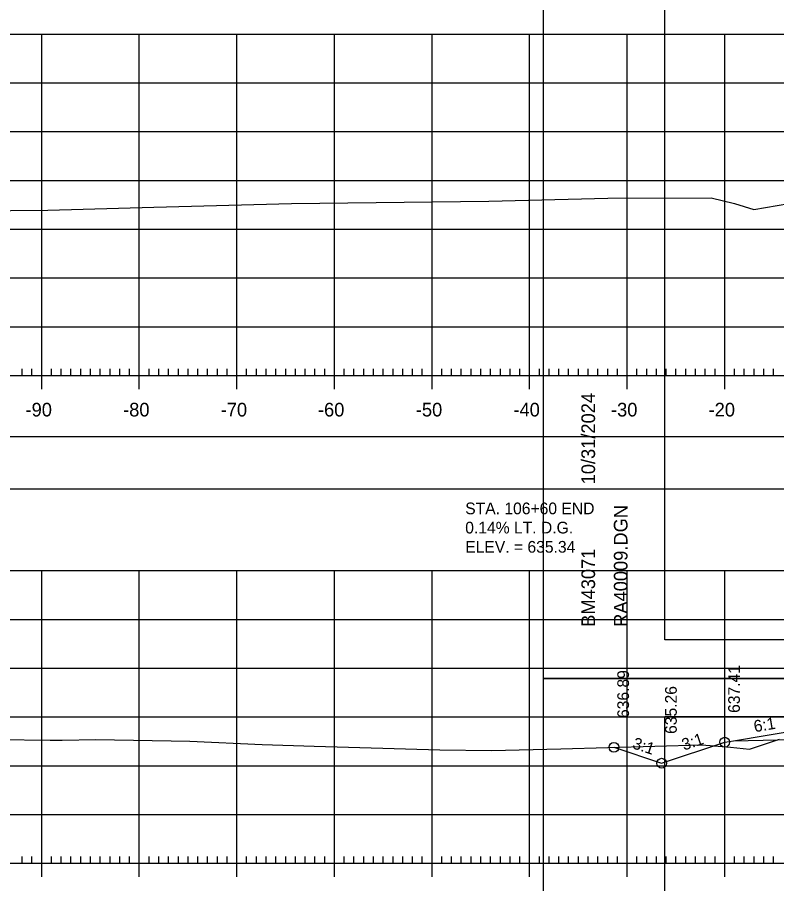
# Model space of a CAD drawing. Extents: x 1381471 to 1382703, y 370300 to 371487.
# Drawn here: x 1381912.3 to 1381990.1, y 371039.5 to 371128.3 of the extents above; entities that cross this region are included whole.
import ezdxf

# ---------------------------------------------------------------- set-up
doc = ezdxf.new("R2010")
doc.units = 0
for name, color, linetype in [('Level 18', 7, 'Continuous'), ('Level 2', 7, 'Continuous'), ('Level 20', 7, 'Continuous'), ('Level 22', 7, 'Continuous'), ('Level 26', 7, 'Continuous'), ('Level 4', 7, 'Continuous'), ('Level 41', 7, 'Continuous'), ('Level 42', 7, 'Continuous'), ('Level 45', 7, 'Continuous'), ('Level 5', 7, 'Continuous'), ('Level 6', 7, 'Continuous')]:
    doc.layers.add(name, color=color, linetype=linetype)

msp = doc.modelspace()

# ---------------------------------------------------------------- linework, layer by layer
at = {"layer": 'Level 18'}
for points in [[(1381864.772, 371108.078), (1381865.976, 371108.088), (1381873.71, 371108.053), (1381885.41, 371108.295), (1381892.552, 371108.284), (1381915.382, 371108.479), (1381926.247, 371108.792), (1381940.386, 371109.168), (1381960.604, 371109.403), (1381972.783, 371109.721), (1381983.377, 371109.751), (1381985.775, 371109.162), (1381987.759, 371108.574), (1381991.332, 371109.19)], [(1381864.772, 371053.733), (1381866.819, 371053.78), (1381877.788, 371053.995), (1381883.886, 371054.108), (1381892.68, 371054.277), (1381899.926, 371054.23), (1381905.023, 371054.302), (1381915.624, 371054.159), (1381916.856, 371054.17), (1381920.322, 371054.218), (1381929.942, 371054.047), (1381937.36, 371053.717), (1381942.702, 371053.56), (1381955.573, 371053.183), (1381960.873, 371053.094), (1381967.986, 371053.284), (1381982.422, 371053.683), (1381985.357, 371053.452), (1381987.306, 371053.246), (1381990.383, 371054.284)]]:
    msp.add_lwpolyline(points, dxfattribs=at)
at = {"layer": 'Level 2'}
msp.add_lwpolyline([(1381985.66, 371054.107), (1381994.762, 371054.289), (1381994.772, 371055.206), (1382004.772, 371055.406), (1382014.772, 371055.202), (1382014.782, 371054.286), (1382023.908, 371054.103)], dxfattribs=at)
at = {"layer": 'Level 20'}
msp.add_lwpolyline([(1381973.409, 371053.434), (1381978.303, 371051.803), (1381984.772, 371053.959), (1381985.66, 371054.107), (1381992.772, 371055.292), (1381994.772, 371055.372), (1382004.772, 371055.572), (1382014.772, 371055.372), (1382016.772, 371055.292), (1382023.908, 371054.103), (1382024.772, 371053.959), (1382031.554, 371051.698)], dxfattribs=at)
at = {"layer": 'Level 22'}
for p, q in [((1381864.772, 371126.544), (1382144.772, 371126.544)), ((1381914.772, 371091.544), (1381914.772, 371126.544)), ((1381924.772, 371091.544), (1381924.772, 371126.544)), ((1381934.772, 371091.544), (1381934.772, 371126.544)), ((1381944.772, 371091.544), (1381944.772, 371126.544)), ((1381954.772, 371091.544), (1381954.772, 371126.544)), ((1381964.772, 371091.544), (1381964.772, 371126.544)), ((1381974.772, 371091.544), (1381974.772, 371126.544)), ((1381984.772, 371091.544), (1381984.772, 371126.544)), ((1381864.772, 371121.544), (1382144.772, 371121.544)), ((1381864.772, 371116.544), (1382144.772, 371116.544)), ((1381864.772, 371111.544), (1382144.772, 371111.544)), ((1381864.772, 371106.544), (1382144.772, 371106.544)), ((1381864.772, 371101.544), (1382144.772, 371101.544)), ((1381864.772, 371096.544), (1382144.772, 371096.544)), ((1381864.772, 371091.544), (1382144.772, 371091.544)), ((1381864.772, 371071.544), (1382144.772, 371071.544)), ((1381914.772, 371041.544), (1381914.772, 371071.544)), ((1381924.772, 371041.544), (1381924.772, 371071.544)), ((1381934.772, 371041.544), (1381934.772, 371071.544)), ((1381944.772, 371041.544), (1381944.772, 371071.544)), ((1381954.772, 371041.544), (1381954.772, 371071.544)), ((1381964.772, 371041.544), (1381964.772, 371071.544)), ((1381974.772, 371041.544), (1381974.772, 371071.544)), ((1381984.772, 371041.544), (1381984.772, 371071.544)), ((1381864.772, 371066.544), (1382144.772, 371066.544)), ((1381864.772, 371061.544), (1382144.772, 371061.544)), ((1381864.772, 371056.544), (1382144.772, 371056.544)), ((1381864.772, 371051.544), (1382144.772, 371051.544)), ((1381864.772, 371046.544), (1382144.772, 371046.544)), ((1381864.772, 371041.544), (1382144.772, 371041.544))]:
    msp.add_line(p, q, dxfattribs=at)
at = {"layer": 'Level 26'}
for centre in [(1381984.772, 371053.959), (1381973.409, 371053.434), (1381978.303, 371051.803), (1381978.303, 371051.803)]:
    msp.add_circle(centre, 0.5, dxfattribs=at)
at = {"layer": 'Level 4'}
for p, q in [((1381914.772, 371090.144), (1381914.772, 371092.944)), ((1381924.772, 371090.144), (1381924.772, 371092.944)), ((1381934.772, 371090.144), (1381934.772, 371092.944)), ((1381944.772, 371090.144), (1381944.772, 371092.944)), ((1381954.772, 371090.144), (1381954.772, 371092.944)), ((1381964.772, 371090.144), (1381964.772, 371092.944)), ((1381974.772, 371090.144), (1381974.772, 371092.944)), ((1381984.772, 371090.144), (1381984.772, 371092.944)), ((1381864.772, 371091.544), (1382144.772, 371091.544)), ((1381912.772, 371091.544), (1381912.772, 371092.244)), ((1381913.772, 371091.544), (1381913.772, 371092.244)), ((1381915.772, 371091.544), (1381915.772, 371092.244)), ((1381916.772, 371091.544), (1381916.772, 371092.244)), ((1381917.772, 371091.544), (1381917.772, 371092.244)), ((1381918.772, 371091.544), (1381918.772, 371092.244)), ((1381919.772, 371091.544), (1381919.772, 371092.244)), ((1381920.772, 371091.544), (1381920.772, 371092.244)), ((1381921.772, 371091.544), (1381921.772, 371092.244)), ((1381922.772, 371091.544), (1381922.772, 371092.244)), ((1381923.772, 371091.544), (1381923.772, 371092.244)), ((1381925.772, 371091.544), (1381925.772, 371092.244)), ((1381926.772, 371091.544), (1381926.772, 371092.244)), ((1381927.772, 371091.544), (1381927.772, 371092.244)), ((1381928.772, 371091.544), (1381928.772, 371092.244)), ((1381929.772, 371091.544), (1381929.772, 371092.244)), ((1381930.772, 371091.544), (1381930.772, 371092.244)), ((1381931.772, 371091.544), (1381931.772, 371092.244)), ((1381932.772, 371091.544), (1381932.772, 371092.244)), ((1381933.772, 371091.544), (1381933.772, 371092.244)), ((1381935.772, 371091.544), (1381935.772, 371092.244)), ((1381936.772, 371091.544), (1381936.772, 371092.244)), ((1381937.772, 371091.544), (1381937.772, 371092.244)), ((1381938.772, 371091.544), (1381938.772, 371092.244)), ((1381939.772, 371091.544), (1381939.772, 371092.244)), ((1381940.772, 371091.544), (1381940.772, 371092.244)), ((1381941.772, 371091.544), (1381941.772, 371092.244)), ((1381942.772, 371091.544), (1381942.772, 371092.244)), ((1381943.772, 371091.544), (1381943.772, 371092.244)), ((1381945.772, 371091.544), (1381945.772, 371092.244)), ((1381946.772, 371091.544), (1381946.772, 371092.244)), ((1381947.772, 371091.544), (1381947.772, 371092.244)), ((1381948.772, 371091.544), (1381948.772, 371092.244)), ((1381949.772, 371091.544), (1381949.772, 371092.244)), ((1381950.772, 371091.544), (1381950.772, 371092.244)), ((1381951.772, 371091.544), (1381951.772, 371092.244)), ((1381952.772, 371091.544), (1381952.772, 371092.244)), ((1381953.772, 371091.544), (1381953.772, 371092.244)), ((1381955.772, 371091.544), (1381955.772, 371092.244)), ((1381956.772, 371091.544), (1381956.772, 371092.244)), ((1381957.772, 371091.544), (1381957.772, 371092.244)), ((1381958.772, 371091.544), (1381958.772, 371092.244)), ((1381959.772, 371091.544), (1381959.772, 371092.244)), ((1381960.772, 371091.544), (1381960.772, 371092.244)), ((1381961.772, 371091.544), (1381961.772, 371092.244)), ((1381962.772, 371091.544), (1381962.772, 371092.244)), ((1381963.772, 371091.544), (1381963.772, 371092.244)), ((1381965.772, 371091.544), (1381965.772, 371092.244)), ((1381966.772, 371091.544), (1381966.772, 371092.244)), ((1381967.772, 371091.544), (1381967.772, 371092.244)), ((1381968.772, 371091.544), (1381968.772, 371092.244)), ((1381969.772, 371091.544), (1381969.772, 371092.244)), ((1381970.772, 371091.544), (1381970.772, 371092.244)), ((1381971.772, 371091.544), (1381971.772, 371092.244)), ((1381972.772, 371091.544), (1381972.772, 371092.244)), ((1381973.772, 371091.544), (1381973.772, 371092.244)), ((1381975.772, 371091.544), (1381975.772, 371092.244)), ((1381976.772, 371091.544), (1381976.772, 371092.244)), ((1381977.772, 371091.544), (1381977.772, 371092.244)), ((1381978.772, 371091.544), (1381978.772, 371092.244)), ((1381979.772, 371091.544), (1381979.772, 371092.244)), ((1381980.772, 371091.544), (1381980.772, 371092.244)), ((1381981.772, 371091.544), (1381981.772, 371092.244)), ((1381982.772, 371091.544), (1381982.772, 371092.244)), ((1381983.772, 371091.544), (1381983.772, 371092.244)), ((1381985.772, 371091.544), (1381985.772, 371092.244)), ((1381986.772, 371091.544), (1381986.772, 371092.244)), ((1381987.772, 371091.544), (1381987.772, 371092.244)), ((1381988.772, 371091.544), (1381988.772, 371092.244)), ((1381989.772, 371091.544), (1381989.772, 371092.244)), ((1381914.772, 371040.144), (1381914.772, 371042.944)), ((1381924.772, 371040.144), (1381924.772, 371042.944)), ((1381934.772, 371040.144), (1381934.772, 371042.944)), ((1381944.772, 371040.144), (1381944.772, 371042.944)), ((1381954.772, 371040.144), (1381954.772, 371042.944)), ((1381964.772, 371040.144), (1381964.772, 371042.944)), ((1381974.772, 371040.144), (1381974.772, 371042.944)), ((1381984.772, 371040.144), (1381984.772, 371042.944)), ((1381912.772, 371041.544), (1381912.772, 371042.244)), ((1381913.772, 371041.544), (1381913.772, 371042.244)), ((1381915.772, 371041.544), (1381915.772, 371042.244)), ((1381916.772, 371041.544), (1381916.772, 371042.244)), ((1381917.772, 371041.544), (1381917.772, 371042.244)), ((1381918.772, 371041.544), (1381918.772, 371042.244)), ((1381919.772, 371041.544), (1381919.772, 371042.244)), ((1381920.772, 371041.544), (1381920.772, 371042.244)), ((1381921.772, 371041.544), (1381921.772, 371042.244)), ((1381922.772, 371041.544), (1381922.772, 371042.244)), ((1381923.772, 371041.544), (1381923.772, 371042.244)), ((1381925.772, 371041.544), (1381925.772, 371042.244)), ((1381926.772, 371041.544), (1381926.772, 371042.244)), ((1381927.772, 371041.544), (1381927.772, 371042.244)), ((1381928.772, 371041.544), (1381928.772, 371042.244)), ((1381929.772, 371041.544), (1381929.772, 371042.244)), ((1381930.772, 371041.544), (1381930.772, 371042.244)), ((1381931.772, 371041.544), (1381931.772, 371042.244)), ((1381932.772, 371041.544), (1381932.772, 371042.244)), ((1381933.772, 371041.544), (1381933.772, 371042.244)), ((1381935.772, 371041.544), (1381935.772, 371042.244)), ((1381936.772, 371041.544), (1381936.772, 371042.244)), ((1381937.772, 371041.544), (1381937.772, 371042.244)), ((1381938.772, 371041.544), (1381938.772, 371042.244)), ((1381939.772, 371041.544), (1381939.772, 371042.244)), ((1381940.772, 371041.544), (1381940.772, 371042.244)), ((1381941.772, 371041.544), (1381941.772, 371042.244)), ((1381942.772, 371041.544), (1381942.772, 371042.244)), ((1381943.772, 371041.544), (1381943.772, 371042.244)), ((1381945.772, 371041.544), (1381945.772, 371042.244)), ((1381946.772, 371041.544), (1381946.772, 371042.244)), ((1381947.772, 371041.544), (1381947.772, 371042.244)), ((1381948.772, 371041.544), (1381948.772, 371042.244)), ((1381949.772, 371041.544), (1381949.772, 371042.244)), ((1381950.772, 371041.544), (1381950.772, 371042.244)), ((1381951.772, 371041.544), (1381951.772, 371042.244)), ((1381952.772, 371041.544), (1381952.772, 371042.244)), ((1381953.772, 371041.544), (1381953.772, 371042.244)), ((1381955.772, 371041.544), (1381955.772, 371042.244)), ((1381956.772, 371041.544), (1381956.772, 371042.244)), ((1381957.772, 371041.544), (1381957.772, 371042.244)), ((1381958.772, 371041.544), (1381958.772, 371042.244)), ((1381959.772, 371041.544), (1381959.772, 371042.244)), ((1381960.772, 371041.544), (1381960.772, 371042.244)), ((1381961.772, 371041.544), (1381961.772, 371042.244)), ((1381962.772, 371041.544), (1381962.772, 371042.244)), ((1381963.772, 371041.544), (1381963.772, 371042.244)), ((1381965.772, 371041.544), (1381965.772, 371042.244)), ((1381966.772, 371041.544), (1381966.772, 371042.244)), ((1381967.772, 371041.544), (1381967.772, 371042.244)), ((1381968.772, 371041.544), (1381968.772, 371042.244)), ((1381969.772, 371041.544), (1381969.772, 371042.244)), ((1381970.772, 371041.544), (1381970.772, 371042.244)), ((1381971.772, 371041.544), (1381971.772, 371042.244)), ((1381972.772, 371041.544), (1381972.772, 371042.244)), ((1381973.772, 371041.544), (1381973.772, 371042.244)), ((1381975.772, 371041.544), (1381975.772, 371042.244)), ((1381976.772, 371041.544), (1381976.772, 371042.244)), ((1381977.772, 371041.544), (1381977.772, 371042.244)), ((1381978.772, 371041.544), (1381978.772, 371042.244)), ((1381979.772, 371041.544), (1381979.772, 371042.244)), ((1381980.772, 371041.544), (1381980.772, 371042.244)), ((1381981.772, 371041.544), (1381981.772, 371042.244)), ((1381982.772, 371041.544), (1381982.772, 371042.244)), ((1381983.772, 371041.544), (1381983.772, 371042.244)), ((1381985.772, 371041.544), (1381985.772, 371042.244)), ((1381986.772, 371041.544), (1381986.772, 371042.244)), ((1381987.772, 371041.544), (1381987.772, 371042.244)), ((1381988.772, 371041.544), (1381988.772, 371042.244)), ((1381989.772, 371041.544), (1381989.772, 371042.244)), ((1381864.772, 371041.544), (1382144.772, 371041.544))]:
    msp.add_line(p, q, dxfattribs=at)
at = {"layer": 'Level 45'}
for p, q in [((1381978.613, 371064.458), (1381978.613, 371269.918)), ((1381978.613, 371064.458), (1381978.613, 371064.458)), ((1382294.793, 371064.458), (1381978.613, 371064.458)), ((1381966.213, 371060.48), (1382299.546, 371060.48)), ((1381966.213, 371060.475), (1382299.546, 371060.475)), ((1381978.613, 371056.58), (1382294.793, 371056.58)), ((1381978.613, 370851.12), (1381978.613, 371056.58))]:
    msp.add_line(p, q, dxfattribs=at)
for points in [[(1381966.206, 371273.813), (1382299.546, 371273.813), (1382299.546, 371060.475), (1381966.206, 371060.475)], [(1382212.533, 371269.918), (1382232.153, 371269.918), (1382232.153, 371260.038), (1382248.266, 371260.038), (1382271.465, 371260.038), (1382271.465, 371235.706), (1382294.793, 371235.706), (1382294.793, 371064.458), (1381978.613, 371064.458), (1381978.613, 371269.918)], [(1381966.206, 371060.475), (1382299.546, 371060.475), (1382299.546, 370847.137), (1381966.206, 370847.137)], [(1382212.533, 371056.58), (1382232.153, 371056.58), (1382232.153, 371046.7), (1382248.266, 371046.7), (1382271.465, 371046.7), (1382271.465, 371022.368), (1382294.793, 371022.368), (1382294.793, 370851.12), (1381978.613, 370851.12), (1381978.613, 371056.58)]]:
    msp.add_lwpolyline(points, close=True, dxfattribs=at)
at = {"layer": 'Level 6'}
msp.add_lwpolyline([(1381850.409, 371079.931), (1382159.135, 371079.931), (1382159.135, 371085.253), (1381850.409, 371085.253)], close=True, dxfattribs=at)

# ---------------------------------------------------------------- texts
at = {"layer": 'Level 41'}
for s, p in [('637.41', (1381986.322, 371056.959)), ('636.89', (1381974.959, 371056.434)), ('635.26', (1381979.853, 371054.803))]:
    msp.add_text(s, height=1.2, rotation=90, dxfattribs=at).set_placement(p)
at = {"layer": 'Level 42'}
for s, rotation, p in [('6:1', 9.46232, (1381987.842, 371054.977)), ('3:1', 341.56507, (1381975.225, 371053.356)), ('3:1', 18.43493, (1381980.591, 371053.092))]:
    msp.add_text(s, height=1.2, rotation=rotation, dxfattribs=at).set_placement(p)
at = {"layer": 'Level 45'}
for s, p in [('10/31/2024', (1381971.479, 371080.386)), ('RA40009.DGN', (1381974.804, 371065.783)), ('BM43071', (1381971.479, 371065.783))]:
    msp.add_text(s, height=1.4, rotation=90, dxfattribs=at).set_placement(p)
at = {"layer": 'Level 5'}
for s, height, p in [('-90', 1.4, (1381913.113, 371087.344)), ('-80', 1.4, (1381923.113, 371087.344)), ('-70', 1.4, (1381933.113, 371087.344)), ('-60', 1.4, (1381943.08, 371087.344)), ('-50', 1.4, (1381953.113, 371087.344)), ('-40', 1.4, (1381963.113, 371087.344)), ('-30', 1.4, (1381973.113, 371087.344)), ('-20', 1.4, (1381983.113, 371087.344)), ('STA. 106+60 END', 1.2, (1381958.172, 371077.32)), ('0.14% LT. D.G. ', 1.2, (1381958.172, 371075.352)), ('ELEV. = 635.34', 1.2, (1381958.172, 371073.384))]:
    msp.add_text(s, height=height, dxfattribs=at).set_placement(p)

doc.saveas('drawing.dxf')
